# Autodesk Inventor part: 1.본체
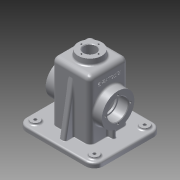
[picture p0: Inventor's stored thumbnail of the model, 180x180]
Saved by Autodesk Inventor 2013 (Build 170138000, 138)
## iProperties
Created: 2016-01
Part Number: 1.본체
Material: 알루미늄 6061
Document SubType Name: Modeling
Designer: Administrator
Density: 2.71 g/cm^3
Mass: 803.316 g
Surface Area: 909.833 cm^2
Volume: 296.427 cm^3
Author: Administrator
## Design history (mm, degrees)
sketch "스케치1"
  geometry: L1 (-65, 57.5)-(65, 57.5); L2 (65, 57.5)-(65, -57.5); L3 (65, -57.5)-(-65, -57.5); L4 (-65, -57.5)-(-65, 57.5); 3 further points
  constraints: 8 end point, 2 midpoint, 2 parallel, 1 horizontal, 1 horizontal alignment, 1 perpendicular, 1 vertical alignment
  dimensions: "d0" = 130 distance of L2.end L3.end; "d2" = 115 distance of L1.end L2.end
extrude "돌출1" new body sketch "스케치1" distance "d3" = 8; taper "d4" = 0 deg
sketch "스케치2"
  geometry: L1 (65, 57.5)-(-65, 57.5) reference; L2 (-65, 57.5)-(-65, -57.5) reference; L3 (-65, -57.5)-(65, -57.5) reference; L4 (65, -57.5)-(65, 57.5) reference; L5 (-60, -52.5)-(-60, 52.5); L6 (-60, 52.5)-(60, 52.5); L7 (60, 52.5)-(60, -52.5); L8 (60, -52.5)-(-60, -52.5); 1 further point
  constraints: 8 end point, 3 other
  dimensions: "d5" = 5 distance between parallel lines of L3 L8
extrude "돌출2" join sketch "스케치2" distance "d6" = 2; taper "d7" = 0 deg
sketch "스케치3"
  geometry: L1 (-32.5, 32.5)-(32.5, 32.5); L2 (32.5, 32.5)-(32.5, -32.5); L3 (32.5, -32.5)-(-32.5, -32.5); L4 (-32.5, -32.5)-(-32.5, 32.5); 3 further points
  constraints: 8 end point, 2 midpoint, 2 parallel, 1 horizontal, 1 horizontal alignment, 1 perpendicular, 1 vertical alignment
  dimensions: "d8" = 65 distance of L3.end L1.start; "d10" = 65 distance of L1.start L1.end
extrude "돌출3" join sketch "스케치3" distance "d11" = 100; taper "d12" = 0 deg
sketch "스케치4"
  geometry: L1 (-27.5, -27.5)-(27.5, -27.5); L2 (27.5, -27.5)-(27.5, 27.5); L3 (27.5, 27.5)-(-27.5, 27.5); L4 (-27.5, 27.5)-(-27.5, -27.5); 3 further points
  constraints: 8 end point, 2 midpoint, 2 parallel, 1 horizontal, 1 horizontal alignment, 1 perpendicular, 1 vertical alignment
  dimensions: "d13" = 55 distance of L3.end L1.start; "d15" = 55 distance of L1.start L1.end
extrude "돌출4" cut sketch "스케치4" distance "d16" = 105; taper "d17" = 0 deg
node "작업 평면1"
sketch "스케치5"
  geometry: C1 r 20 at (0, 0); 1 further point
  constraints: 1 centre point, 1 coincident
  dimensions: "d19" = 40 diameter of C1
extrude "돌출5" join sketch "스케치5" stored distance "d20" = 105; taper "d21" = 0 deg
hole "구멍1" diameter "d24" = 21; stored, may be unused: countersink angle "d28" = 90 deg, drill point angle "d30" = 118 deg; dims "d22" = 10, "d23" = 10, "d25" = 6, "d26" = 4, "d27" = 2, "d29" = 23
node "작업 평면3"
sketch "스케치6"
  geometry: L1 (10, 5)-(10, 60) reference; C1 r 27.5 at (-45, 32.5); 1 further point
  constraints: 1 centre point, 1 horizontal alignment
  dimensions: "d32" = 55 distance from line of C1.centre L1; "d33" = 55 diameter of C1
extrude "돌출6" join sketch "스케치6" stored distance "d34" = 105; taper "d35" = 0 deg
hole "구멍2" diameter "d38" = 30; stored, may be unused: countersink angle "d42" = 90 deg, drill point angle "d44" = 0 deg; dims "d36" = 10, "d37" = 10, "d39" = 6, "d40" = 35, "d41" = 17, "d43" = 23
feature "면 기울기1" dims angle "d45" = 5 deg
sketch "스케치7"
  geometry: L1 (-42.5, 25.5)-(-42.5, 8); L2 (20, 118)-(20.875, 108) reference; L3 (20.875, 108)-(32.5, 108) reference; L4 (32.5, 108)-(32.5, 80.5) reference; L5 (32.5, 80.5)-(47.5, 80.5) reference; L6 (47.5, 80.5)-(47.5, 70.5) reference; L7 (47.5, 70.5)-(30.5, 70.5) reference; L8 (30.5, 70.5)-(30.5, 68) reference; L9 (30.5, 68)-(27.5, 68) reference; L10 (27.5, 68)-(27.5, 103) reference; L11 (27.5, 103)-(10.5, 103) reference; L12 (10.5, 103)-(10.5, 118) reference; L13 (10.5, 118)-(20, 118) reference; L14 (-20.875, 108)-(-20, 118) reference; L15 (-20, 118)-(-10.5, 118) reference; L16 (-10.5, 118)-(-10.5, 103) reference; L17 (-10.5, 103)-(-27.5, 103) reference; L18 (-27.5, 103)-(-27.5, 68) reference; L19 (-27.5, 68)-(-30.5, 68) reference; L20 (-30.5, 68)-(-30.5, 70.5) reference; L21 (-30.5, 70.5)-(-47.5, 70.5) reference; L22 (-47.5, 70.5)-(-47.5, 80.5) reference; L23 (-47.5, 80.5)-(-32.5, 80.5) reference; L24 (-32.5, 80.5)-(-32.5, 108) reference; L25 (-32.5, 108)-(-20.875, 108) reference; L26 (-65, 0)-(-65, 8) reference; L27 (-65, 8)-(-32.5, 8) reference; L28 (-32.5, 8)-(-32.5, 25.5) reference; L29 (-32.5, 25.5)-(-47.5, 25.5) reference; L30 (-47.5, 25.5)-(-47.5, 35.5) reference; L31 (-47.5, 35.5)-(-30.5, 35.5) reference; L32 (-30.5, 35.5)-(-30.5, 38) reference; L33 (-30.5, 38)-(-27.5, 38) reference; L34 (-27.5, 38)-(-27.5, -2) reference; L35 (-27.5, -2)-(-60, -2) reference; L36 (-60, -2)-(-60, 0) reference; L37 (-60, 0)-(-65, 0) reference; L38 (65, 8)-(65, 0) reference; L39 (65, 0)-(60, 0) reference; L40 (60, 0)-(60, -2) reference; L41 (60, -2)-(27.5, -2) reference; L42 (27.5, -2)-(27.5, 38) reference; L43 (27.5, 38)-(30.5, 38) reference; L44 (30.5, 38)-(30.5, 35.5) reference; L45 (30.5, 35.5)-(47.5, 35.5) reference; L46 (47.5, 35.5)-(47.5, 25.5) reference; L47 (47.5, 25.5)-(32.5, 25.5) reference; L48 (32.5, 25.5)-(32.5, 8) reference; L49 (32.5, 8)-(65, 8) reference; 1 further point
  constraints: 2 end point, 2 horizontal alignment, 1 vertical
  dimensions: "d46" = 15 distance between parallel lines of L1 L34
feature "리브1" sketch "스케치7" dims "d47" = 1, "d48" = 6, "d49" = 0, "d50" = 0, "d51" = 1, "d52" = 1
sketch "스케치8"
  geometry: L1 (-32.5, 108)-(-20.875, 108) reference; L2 (-20.875, 108)-(-20, 118) reference; L3 (-20, 118)-(-10.5, 118) reference; L4 (-10.5, 118)-(-10.5, 103) reference; L5 (-10.5, 103)-(-27.5, 103) reference; L6 (-27.5, 103)-(-27.5, -2) reference; L7 (-27.5, -2)-(-52.5, -2) reference; L8 (-52.5, -2)-(-52.5, 0) reference; L9 (-52.5, 0)-(-57.5, 0) reference; L10 (-57.5, 0)-(-57.5, 8) reference; L11 (-57.5, 8)-(-32.5, 8) reference; L12 (-32.5, 8)-(-32.5, 108) reference; L13 (20.875, 108)-(32.5, 108) reference; L14 (32.5, 108)-(32.5, 8) reference; L15 (32.5, 8)-(57.5, 8) reference; L16 (57.5, 8)-(57.5, 0) reference; L17 (57.5, 0)-(52.5, 0) reference; L18 (52.5, 0)-(52.5, -2) reference; L19 (52.5, -2)-(27.5, -2) reference; L20 (27.5, -2)-(27.5, 103) reference; L21 (27.5, 103)-(10.5, 103) reference; L22 (10.5, 103)-(10.5, 118) reference; L23 (10.5, 118)-(20, 118) reference; L24 (20, 118)-(20.875, 108) reference; L25 (-47.5, 8)-(-32.5, 93.069); 1 further point
  constraints: 2 end point, 2 point on line
  dimensions: "d54" = 10 deg angle of L25 L10; "d55" = 10 distance of L10.end L25.start
feature "리브2" sketch "스케치8" dims "d56" = 1, "d57" = 10, "d58" = 0, "d59" = 0, "d60" = 1, "d61" = 1
fillet "모깎기1" dims "d62" = 15
sketch "스케치9"
  geometry: C1 r 7.5 at (-50, 42.5); A1 r 15 centre (-50, 42.5) between (-50, 57.5) and (-65, 42.5) reference; 1 further point
  constraints: 1 centre point, 1 coincident
  dimensions: "d63" = 15 diameter of C1
extrude "돌출7" join sketch "스케치9" distance "d64" = 3; taper "d65" = 0 deg
hole "구멍3" diameter "d68" = 5; stored, may be unused: countersink angle "d72" = 90 deg, drill point angle "d74" = 0 deg; dims "d66" = 10, "d67" = 10, "d69" = 6, "d70" = 35, "d71" = 17, "d73" = 23
fillet "모깎기2" dims "d81" = 8
fillet "모깎기3" dims "d82" = 8
fillet "모깎기4" dims "d83" = 3
fillet "모깎기5" dims "d84" = 3
fillet "모깎기6" dims "d85" = 3
fillet "모깎기7" dims "d86" = 3
fillet "모깎기8" dims "d87" = 1
sketch "스케치10"
  geometry: C1 r 17.5 at (0, 0) reference; 2 further points
  constraints: 1 horizontal alignment
  dimensions: "d88" = 21 distance of C1.centre point (-21, 0)
hole "구멍4" sketch "스케치10" at (-21, 0) diameter "d89" = 3.242; stored, may be unused: countersink angle "d93" = 90 deg, drill point angle "d95" = 118 deg; dims "d90" = 8, "d91" = 35, "d92" = 17, "d94" = 10
sketch "스케치11"
  geometry: C1 r 10.5 at (0, 0) reference; 1 further point
  constraints: 1 vertical alignment
  dimensions: "d99" = 14.5 distance of point (0, 14.5) C1.centre
hole "구멍5" sketch "스케치11" at (0, 14.5) diameter "d100" = 2.459; stored, may be unused: countersink angle "d104" = 90 deg, drill point angle "d106" = 118 deg; dims "d101" = 7, "d102" = 35, "d103" = 17, "d105" = 9
fillet "모깎기9" dims "d110" = 3
fillet "모깎기10" dims "d111" = 10
fillet "모깎기11" dims "d112" = 0.3
chamfer "모따기1" distance "d113" = 1; stored, may be unused: second distance "d114" = 2, angle "d115" = 45 deg
sketch "스케치12"
  geometry: L1 (-18, 4.5)-(-18, 44.5) reference; A1 r 30.5 centre (47, 24.5) between (28.834, 49) and (28.834, 0) reference; 2 further points
  constraints: 1 horizontal alignment, 1 other
  dimensions: "d116" = 27 distance from line of point (9, 24.5) L1
feature "엠보싱1" sketch "스케치12" dims "d117" = 0.5, "d118" = 0
fillet "모깎기12" dims "d119" = 3
node "솔리드1"
mirror "대칭2"
mirror "대칭3"
mirror "대칭4"
pattern_linear "직사각형 패턴1" dims "d77" = 85
pattern_circular "원형 패턴1" dims angle "d97" = 360 deg
mirror "대칭5"
pattern_circular "원형 패턴2" dims angle "d108" = 360 deg
node "절단 모서리 투영1"
node "절단 모서리 투영2"
other parameters: "d31" = 15
